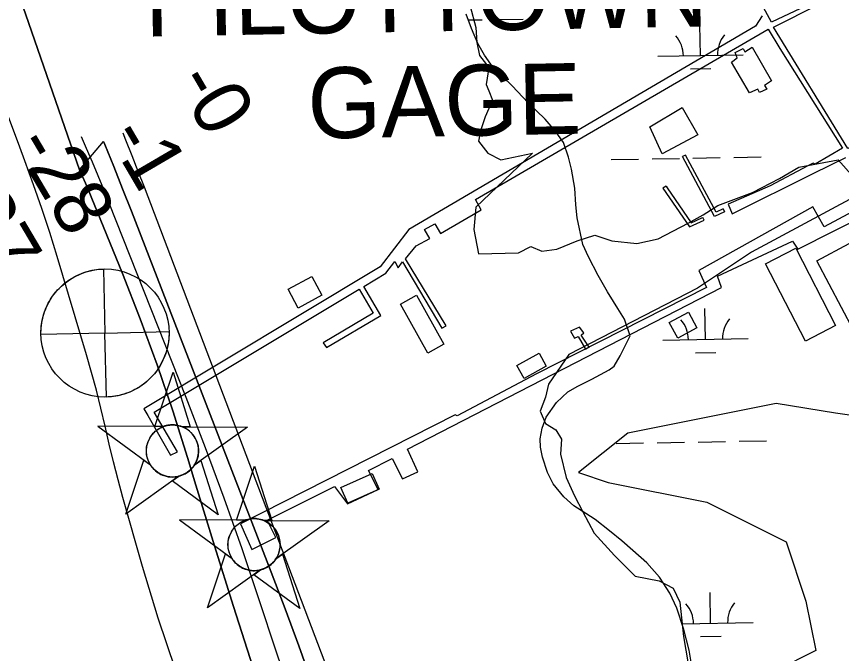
# Model space of a CAD drawing. Extents: x 3914892 to 3953151, y 242587 to 268572.
# Drawn here: x 3942580 to 3943546, y 252639 to 253385 of the extents above; entities that cross this region are included whole.
import ezdxf

# ---------------------------------------------------------------- set-up
doc = ezdxf.new("R2010")
doc.units = 0
for name, color, linetype in [('V-BLDG-OTLN', 7, 'Continuous'), ('V-CHAN-DOCK', 7, 'Continuous'), ('V-CHAN-NAID', 7, 'Continuous'), ('V-RIVR-EDGE', 7, 'Continuous'), ('V-RIVR-GAGE', 7, 'Continuous'), ('V-RIVR-GAGE-IDEN', 7, 'Continuous'), ('V-RIVR-RANG', 7, 'Continuous'), ('V-SITE-VEGE', 7, 'Continuous'), ('V-TOPO-DPTH', 7, 'Continuous'), ('V-TOPO-MINR', 7, 'Continuous'), ('V-WETL-SWMP', 7, 'Continuous')]:
    doc.layers.add(name, color=color, linetype=linetype)

msp = doc.modelspace()

# ---------------------------------------------------------------- linework, layer by layer
at = {"layer": 'V-BLDG-OTLN'}
for points in [[(3943417, 253331.86), (3943423.67, 253336.87), (3943421.34, 253343.11), (3943430.75, 253348.15), (3943432.92, 253344.14), (3943441.29, 253349.45), (3943463.91, 253309.93), (3943455.8, 253304.48), (3943458.62, 253300.32), (3943449.81, 253296.52), (3943447.9, 253300.14), (3943438.29, 253295.95)], [(3943336.08, 253224.42), (3943321.33, 253256.07), (3943359.56, 253278.89), (3943377.83, 253246.94)], [(3943517.03, 253099.31), (3943555.12, 253119.5), (3943566.64, 253097.78), (3943579.97, 253104.84), (3943589.66, 253086.57), (3943583.06, 253083.07), (3943593.52, 253063.35), (3943585.51, 253059.11), (3943597.32, 253036.84), (3943560.5, 253017.32)], [(3943492.55, 253113.96), (3943539.11, 253023.37), (3943503.75, 253005.2), (3943457.19, 253095.79)], [(3942909.55, 253043.89), (3942897.75, 253065.86), (3942925.67, 253080.85), (3942937.47, 253058.88)], [(3943061.36, 252991.07), (3943029.5, 253048.56), (3943048.19, 253058.92), (3943080.04, 253001.42)], [(3943344.27, 253026.99), (3943366.66, 253039.2), (3943376.69, 253020.81), (3943354.31, 253008.6)], [(3943165.83, 252976.54), (3943191.84, 252990.9), (3943200.23, 252975.7), (3943174.22, 252961.33)], [(3942959.64, 252833.66), (3942996.27, 252849.94), (3943004.41, 252831.62), (3942967.78, 252815.34)]]:
    msp.add_lwpolyline(points, close=True, dxfattribs=at)
at = {"layer": 'V-CHAN-DOCK'}
for points in [[(3943517.92, 253404.24), (3943463.83, 253378.69), (3943440.14, 253422.8)], [(3943769.62, 252904.45), (3943816.19, 252933.69), (3943813.48, 252938.9), (3943766.51, 252909.67), (3943720.5, 252982.34), (3943756.42, 253018.48), (3943752.48, 253021.72), (3943717.81, 252989.14), (3943663.2, 253073.87), (3943649.54, 253094.75), (3943601.78, 253155.11), (3943594.76, 253166.35), (3943639.27, 253189.64), (3943635.37, 253196.06), (3943589.27, 253171.99), (3943557.31, 253223.77), (3943607.85, 253252.16), (3943605.92, 253256.57), (3943553.43, 253230.99), (3943466.54, 253373.08), (3943519.85, 253399.84)], [(3943453.19, 253386.4), (3943445.46, 253374.16), (3943039.4, 253135.93), (3943005.77, 253092.19), (3942728.86, 252925.89), (3942733.49, 252918.18), (3942760.13, 252871.42)], [(3942986.34, 253069.25), (3943012.44, 253084.93), (3943022.97, 253098.33), (3943026.86, 253091.11), (3943031.86, 253098.01), (3943077.72, 253020.16), (3943082.89, 253023.24), (3943035.46, 253101.64), (3943047.9, 253116.71), (3943063.94, 253125.25), (3943057.71, 253136.09), (3943069.75, 253142.69), (3943076.36, 253131.06), (3943124.1, 253159.09), (3943117.5, 253171.12), (3943460.14, 253370.78), (3943473.77, 253347.9), (3943547.06, 253231.08), (3943515.36, 253212.39), (3943512.98, 253213.62), (3943506.58, 253210.52), (3943462.47, 253187.22), (3943413.22, 253165.58), (3943417.85, 253154.37), (3943513.63, 253202.06), (3943550.9, 253220.28)], [(3943407.46, 253160.07), (3943399.05, 253156.2), (3943363.32, 253223.17), (3943359.92, 253221.35)], [(3943407.46, 253160.07), (3943409.07, 253156.57), (3943397.36, 253151.19), (3943359.92, 253221.35)], [(3943340.67, 253186.55), (3943336.86, 253184.21), (3943367.8, 253138.89), (3943384.97, 253146.79), (3943383.42, 253149.99)], [(3943340.67, 253186.55), (3943341.72, 253184.77), (3943369.83, 253143.59), (3943382.45, 253149.39), (3943383.42, 253149.99)], [(3943576.04, 253165.8), (3943525.53, 253139), (3943512.3, 253162.27), (3943378.74, 253088.01), (3943388.03, 253067.98), (3943188.82, 252966.74), (3943095.8, 252917.42), (3943093.43, 252918.64), (3942842.12, 252791.02), (3942855.25, 252760.98), (3942883.3, 252774.94), (3942873.23, 252795.38), (3942952.18, 252834.93), (3942967.43, 252814.43), (3943003.49, 252831.46), (3942991.84, 252853.51), (3943019.89, 252867.47), (3943031.92, 252843.82), (3943049.94, 252851.94), (3943037.56, 252878.38), (3943405.55, 253068.15), (3943400.95, 253081.35), (3943488.68, 253122.38), (3943494.92, 253112.74), (3943579.89, 253155.8)], [(3942981.2, 253066.17), (3942997.35, 253038.08), (3942938.96, 253003.23), (3942942.87, 252997.8), (3943006.27, 253035.18), (3942986.34, 253069.25)], [(3942760.13, 252871.42), (3942768.24, 252875.29), (3942740.79, 252921.74), (3942981.2, 253066.17)], [(3943250.31, 252997.99), (3943240.91, 253012.08), (3943244.13, 253014.82), (3943239.04, 253021.66), (3943228.63, 253016.62), (3943233.3, 253008.59), (3943237.7, 253010.53), (3943246.03, 252995.81), (3943250.31, 252997.99)]]:
    msp.add_lwpolyline(points, dxfattribs=at)
at = {"layer": 'V-CHAN-NAID'}
for points in [[(3942751.46, 252905.01), (3942741.87, 252905.08), (3942763, 252968.57), (3942783.22, 252904.79), (3942773.64, 252904.86), (3942772.06, 252905.43), (3942769.96, 252906.05), (3942767.93, 252906.51), (3942765.89, 252906.81), (3942764.72, 252906.93), (3942763.19, 252907.01), (3942761.47, 252907.01), (3942760.1, 252906.94), (3942758.19, 252906.74), (3942756.82, 252906.52), (3942755.04, 252906.13), (3942753.51, 252905.71), (3942752.48, 252905.38)], [(3942751.46, 252905.01), (3942674.97, 252905.56), (3942736.54, 252860.16), (3942735.42, 252862.07), (3942734.61, 252863.69), (3942733.79, 252865.66), (3942733.09, 252867.72), (3942732.73, 252869.04), (3942732.37, 252870.67), (3942732.12, 252872.11), (3942731.93, 252873.71), (3942731.82, 252875.44), (3942731.81, 252877.02), (3942731.92, 252879.1), (3942732.1, 252880.72), (3942732.49, 252882.92), (3942732.98, 252884.84), (3942733.58, 252886.73), (3942734.23, 252888.41), (3942734.96, 252890), (3942735.77, 252891.53), (3942736.83, 252893.27), (3942737.87, 252894.74), (3942738.87, 252896.01), (3942739.87, 252897.15), (3942741.18, 252898.49), (3942742.23, 252899.46), (3942743.95, 252900.85), (3942745.16, 252901.72), (3942746.84, 252902.79), (3942748.58, 252903.74), (3942750.02, 252904.42)], [(3942773.64, 252904.86), (3942850.13, 252904.31), (3942787.93, 252859.79), (3942788.84, 252861.28), (3942789.81, 252863.13), (3942790.53, 252864.71), (3942791.27, 252866.67), (3942791.81, 252868.45), (3942792.21, 252870.09), (3942792.57, 252872.1), (3942792.76, 252873.68), (3942792.88, 252875.88), (3942792.85, 252877.94), (3942792.67, 252880.16), (3942792.4, 252881.92), (3942791.91, 252884.15), (3942791.27, 252886.29), (3942790.52, 252888.27), (3942789.87, 252889.72), (3942788.86, 252891.63), (3942787.8, 252893.36), (3942786.59, 252895.06), (3942785.33, 252896.6), (3942784.05, 252897.96), (3942782.42, 252899.49), (3942780.68, 252900.91), (3942779, 252902.08), (3942777.11, 252903.22), (3942775.64, 252903.98)], [(3942769.9, 252846.89), (3942707.69, 252802.36), (3942728.82, 252865.85), (3942736.54, 252860.16), (3942737.17, 252859.19), (3942738.55, 252857.33), (3942739.77, 252855.92), (3942741.23, 252854.42), (3942742.62, 252853.16), (3942744.08, 252852.01), (3942745.48, 252851.02), (3942747.16, 252849.99), (3942748.87, 252849.07), (3942750.66, 252848.26), (3942752.11, 252847.71), (3942753.73, 252847.18), (3942755.96, 252846.61), (3942757.49, 252846.33), (3942759.52, 252846.07), (3942761.06, 252845.97), (3942762.92, 252845.94), (3942764.6, 252846.02), (3942766.31, 252846.2), (3942768.22, 252846.51)], [(3942787.93, 252859.79), (3942795.72, 252865.37), (3942815.95, 252801.6), (3942762.1, 252841.31), (3942769.9, 252846.89), (3942771.56, 252847.36), (3942773.17, 252847.92), (3942775.33, 252848.84), (3942777.07, 252849.72), (3942778.93, 252850.83), (3942780.67, 252852.05), (3942782.22, 252853.29), (3942783.51, 252854.46), (3942784.89, 252855.88), (3942786.1, 252857.28), (3942787.22, 252858.75)], [(3942847.06, 252795.23), (3942837.47, 252795.3), (3942858.6, 252858.78), (3942878.82, 252795.01), (3942869.23, 252795.08), (3942867.66, 252795.65), (3942865.56, 252796.27), (3942863.52, 252796.72), (3942861.48, 252797.03), (3942860.32, 252797.15), (3942858.78, 252797.23), (3942857.06, 252797.23), (3942855.69, 252797.15), (3942853.79, 252796.95), (3942852.42, 252796.74), (3942850.64, 252796.35), (3942849.11, 252795.93), (3942848.07, 252795.6)], [(3942847.06, 252795.23), (3942770.57, 252795.77), (3942832.13, 252750.38), (3942831.02, 252752.28), (3942830.21, 252753.91), (3942829.38, 252755.88), (3942828.69, 252757.93), (3942828.32, 252759.26), (3942827.96, 252760.88), (3942827.72, 252762.33), (3942827.53, 252763.93), (3942827.42, 252765.66), (3942827.41, 252767.24), (3942827.52, 252769.32), (3942827.7, 252770.93), (3942828.09, 252773.14), (3942828.57, 252775.06), (3942829.17, 252776.95), (3942829.83, 252778.63), (3942830.56, 252780.21), (3942831.37, 252781.75), (3942832.43, 252783.49), (3942833.46, 252784.96), (3942834.46, 252786.23), (3942835.46, 252787.37), (3942836.77, 252788.71), (3942837.82, 252789.67), (3942839.54, 252791.07), (3942840.75, 252791.94), (3942842.44, 252793.01), (3942844.17, 252793.96), (3942845.62, 252794.64)], [(3942869.23, 252795.08), (3942945.73, 252794.53), (3942883.52, 252750.01), (3942884.43, 252751.5), (3942885.41, 252753.35), (3942886.13, 252754.93), (3942886.87, 252756.89), (3942887.41, 252758.67), (3942887.81, 252760.31), (3942888.17, 252762.32), (3942888.35, 252763.89), (3942888.48, 252766.1), (3942888.45, 252768.16), (3942888.26, 252770.38), (3942888, 252772.14), (3942887.5, 252774.37), (3942886.86, 252776.51), (3942886.11, 252778.49), (3942885.47, 252779.94), (3942884.46, 252781.85), (3942883.4, 252783.57), (3942882.18, 252785.28), (3942880.92, 252786.82), (3942879.65, 252788.18), (3942878.02, 252789.71), (3942876.27, 252791.12), (3942874.59, 252792.3), (3942872.71, 252793.43), (3942871.23, 252794.2)], [(3942865.49, 252737.1), (3942803.29, 252692.58), (3942824.41, 252756.07), (3942832.13, 252750.38), (3942832.77, 252749.41), (3942834.15, 252747.55), (3942835.36, 252746.14), (3942836.83, 252744.63), (3942838.22, 252743.38), (3942839.67, 252742.23), (3942841.07, 252741.24), (3942842.75, 252740.2), (3942844.47, 252739.29), (3942846.26, 252738.48), (3942847.7, 252737.93), (3942849.33, 252737.4), (3942851.56, 252736.83), (3942853.09, 252736.55), (3942855.11, 252736.29), (3942856.65, 252736.18), (3942858.51, 252736.16), (3942860.2, 252736.24), (3942861.91, 252736.42), (3942863.81, 252736.73)], [(3942883.52, 252750.01), (3942891.32, 252755.59), (3942911.54, 252691.81), (3942857.69, 252731.52), (3942865.49, 252737.1), (3942867.16, 252737.58), (3942868.77, 252738.14), (3942870.93, 252739.05), (3942872.66, 252739.94), (3942874.53, 252741.05), (3942876.27, 252742.26), (3942877.82, 252743.51), (3942879.11, 252744.68), (3942880.49, 252746.1), (3942881.69, 252747.5), (3942882.81, 252748.97)]]:
    msp.add_lwpolyline(points, close=True, dxfattribs=at)
for centre in [(3942762.35, 252876.48), (3942857.94, 252766.7)]:
    msp.add_circle(centre, 30.54, dxfattribs=at)
at = {"layer": 'V-RIVR-EDGE'}
for points in [[(3943111.08, 253397.55), (3943117.63, 253372.46), (3943118.72, 253355), (3943121.99, 253339.73), (3943132.9, 253325.54), (3943129.63, 253305.91), (3943132.9, 253298.27), (3943137.26, 253287.36), (3943128.54, 253267.72), (3943123.08, 253251.36), (3943120.9, 253239.36), (3943131.81, 253225.18), (3943147.08, 253217.54), (3943184.17, 253225.18), (3943117.63, 253161.9), (3943115.44, 253135.72), (3943120.9, 253107.36), (3943167.81, 253108.45), (3943181.99, 253116.08), (3943195.08, 253110.63), (3943212.54, 253112.81), (3943236.54, 253122.63), (3943257.27, 253129.17), (3943276.9, 253122.63), (3943306.36, 253119.36), (3943331.45, 253124.81), (3943366.36, 253143.36), (3943383.82, 253153.18), (3943401.27, 253164.08), (3943441.64, 253179.36), (3943473.27, 253195.72), (3943496.18, 253208.81), (3943542, 253217.54), (3943560.55, 253196.81)], [(3943560.55, 253173.9), (3943440.55, 253109.54), (3943377.27, 253066.99), (3943226.72, 252989.53), (3943202.72, 252954.62), (3943199.45, 252939.35), (3943192.9, 252922.99), (3943199.45, 252908.8), (3943211.45, 252901.17), (3943217.99, 252890.26), (3943216.9, 252872.8), (3943223.45, 252845.53), (3943233.27, 252823.71), (3943243.08, 252805.16), (3943256.18, 252780.07), (3943280.18, 252753.89), (3943304.18, 252729.89), (3943332.54, 252724.43), (3943348.91, 252715.71), (3943356.54, 252699.34), (3943360.91, 252658.98), (3943369.63, 252608.79)]]:
    msp.add_lwpolyline(points, dxfattribs=at)
at = {"layer": 'V-RIVR-GAGE'}
for points in [[(3942681.64, 253089.61), (3942683.31, 253014.63), (3942608.33, 253012.96), (3942608.31, 253015.06), (3942608.37, 253017.63), (3942608.55, 253020.63), (3942608.85, 253023.6), (3942609.23, 253026.37), (3942609.77, 253029.37), (3942610.34, 253031.96), (3942610.95, 253034.35), (3942611.65, 253036.77), (3942612.56, 253039.53), (3942613.44, 253041.89), (3942614.39, 253044.22), (3942615.53, 253046.75), (3942616.9, 253049.49), (3942618.2, 253051.85), (3942619.54, 253054.11), (3942621.87, 253057.64), (3942623.51, 253059.9), (3942625.67, 253062.62), (3942627.76, 253065.03), (3942629.56, 253066.93), (3942632.27, 253069.58), (3942634.56, 253071.63), (3942636.98, 253073.6), (3942640.04, 253075.89), (3942642.38, 253077.48), (3942644.93, 253079.07), (3942647.87, 253080.73), (3942650.48, 253082.06), (3942653.04, 253083.25), (3942656.64, 253084.73), (3942659.86, 253085.87), (3942663.01, 253086.83), (3942666.25, 253087.66), (3942669.63, 253088.37), (3942673.67, 253089.01), (3942676.66, 253089.33), (3942679.2, 253089.51)], [(3942684.98, 252939.65), (3942683.31, 253014.63), (3942758.29, 253016.3), (3942758.3, 253013.64), (3942758.19, 253010.48), (3942758, 253007.88), (3942757.72, 253005.27), (3942757.26, 253002.13), (3942756.69, 252999.12), (3942755.9, 252995.78), (3942755.31, 252993.62), (3942754.4, 252990.75), (3942753.35, 252987.81), (3942752.31, 252985.24), (3942751.18, 252982.72), (3942749.96, 252980.24), (3942748.67, 252977.85), (3942747.09, 252975.18), (3942745.65, 252972.93), (3942743.6, 252970.01), (3942741.52, 252967.34), (3942738.96, 252964.35), (3942736.72, 252961.98), (3942734.29, 252959.62), (3942732.15, 252957.71), (3942730.54, 252956.37), (3942727.94, 252954.35), (3942726.05, 252953), (3942723.57, 252951.35), (3942720.95, 252949.76), (3942718.27, 252948.27), (3942716.17, 252947.21), (3942713.92, 252946.16), (3942711.33, 252945.06), (3942708.64, 252944.04), (3942705.39, 252942.95), (3942702.25, 252942.06), (3942699.84, 252941.47), (3942697.09, 252940.9), (3942694.72, 252940.5), (3942691.94, 252940.12), (3942689.75, 252939.9), (3942687.18, 252939.73)]]:
    msp.add_lwpolyline(points, close=True, dxfattribs=at)
msp.add_circle((3942683.31, 253014.63), 75, dxfattribs=at)
at = {"layer": 'V-SITE-VEGE'}
msp.add_lwpolyline([(3943620.15, 252908.96), (3943539.05, 252920.54), (3943469.54, 252932.13), (3943295.76, 252897.37), (3943237.84, 252851.03), (3943272.59, 252839.44), (3943388.44, 252816.27), (3943481.13, 252769.93), (3943504.3, 252700.42), (3943515.88, 252642.5), (3943469.54, 252619.33)], dxfattribs=at)
at = {"layer": 'V-TOPO-DPTH'}
for points in [[(3942765.88, 252620.36), (3942745.78, 252680.5), (3942727.27, 252741.21), (3942704.38, 252821.97), (3942698.69, 252842.77), (3942693.25, 252863.62), (3942688.17, 252884.57), (3942683.35, 252905.58), (3942678.48, 252926.58), (3942673.31, 252947.5), (3942667.68, 252968.3), (3942661.74, 252989.02), (3942627.37, 253104.14), (3942618.6, 253132.38), (3942609.44, 253160.49), (3942599.67, 253188.39), (3942589.51, 253216.16), (3942583.4, 253232.3), (3942292.57, 254010.13)], [(3942765.88, 252620.36), (3942745.78, 252680.5), (3942727.27, 252741.21), (3942704.38, 252821.97), (3942698.69, 252842.77), (3942693.25, 252863.62), (3942688.17, 252884.57), (3942683.35, 252905.58), (3942678.48, 252926.58), (3942673.31, 252947.5), (3942667.68, 252968.3), (3942661.74, 252989.02), (3942627.37, 253104.14), (3942618.6, 253132.38), (3942609.44, 253160.49), (3942599.67, 253188.39), (3942589.51, 253216.16), (3942583.4, 253232.3), (3942292.57, 254010.13)], [(3942401.61, 253932.54), (3942653.43, 253205.99), (3942657, 253198.09), (3942660.5, 253190.15), (3942663.89, 253182.16), (3942667.21, 253174.15), (3942703.77, 253084.29), (3942724.57, 253031.06), (3942744.37, 252977.47), (3942762.67, 252923.35), (3942779.97, 252868.88), (3942789.86, 252836.2), (3942811.61, 252765.2), (3942833.72, 252694.32), (3942856.35, 252623.6)], [(3942653.43, 253205.99), (3942681.52, 253239.15), (3942683.01, 253235.6), (3942693.63, 253209.67), (3942704.02, 253183.65), (3942714.25, 253157.56), (3942877.99, 252734.29), (3942894.28, 252691.37), (3942910.21, 252648.32), (3942925.59, 252605.07), (3942940.61, 252561.69), (3942955.68, 252518.33), (3942971.2, 252475.14), (3942987.37, 252432.18), (3943003.98, 252389.39), (3943048.18, 252278.06), (3943056.89, 252256.46), (3943065.75, 252234.92), (3943074.84, 252213.48), (3943084.09, 252192.11), (3943134.63, 252076.98), (3943325.96, 251461.72)], [(3942856.35, 252623.6), (3942833.72, 252694.32), (3942811.61, 252765.2), (3942789.86, 252836.2), (3942779.97, 252868.88), (3942762.67, 252923.35), (3942744.37, 252977.47), (3942724.57, 253031.06), (3942703.77, 253084.29), (3942667.21, 253174.15), (3942663.89, 253182.16), (3942660.5, 253190.15), (3942657, 253198.09), (3942653.43, 253205.99)]]:
    msp.add_lwpolyline(points, dxfattribs=at)
at = {"layer": 'V-TOPO-MINR'}
for points in [[(3942765.88, 252620.36), (3942745.78, 252680.5), (3942727.27, 252741.21), (3942704.38, 252821.97), (3942698.69, 252842.77), (3942693.25, 252863.62), (3942688.17, 252884.57), (3942683.35, 252905.58), (3942678.48, 252926.58), (3942673.31, 252947.5), (3942667.68, 252968.3), (3942661.74, 252989.02), (3942627.37, 253104.14), (3942618.6, 253132.38), (3942609.44, 253160.49), (3942599.67, 253188.39), (3942589.51, 253216.16), (3942583.4, 253232.3), (3942292.57, 254010.13)], [(3942856.35, 252623.6), (3942833.72, 252694.32), (3942811.61, 252765.2), (3942789.86, 252836.2), (3942779.97, 252868.88), (3942762.67, 252923.35), (3942744.37, 252977.47), (3942724.57, 253031.06), (3942703.77, 253084.29), (3942667.21, 253174.15), (3942663.89, 253182.16), (3942660.5, 253190.15), (3942657, 253198.09), (3942653.43, 253205.99), (3942401.61, 253932.54)], [(3942904.14, 252582.34), (3942883.8, 252642.04), (3942863.92, 252701.9), (3942843.83, 252761.68), (3942823, 252821.19), (3942801.08, 252880.31), (3942778.43, 252939.17), (3942688.4, 253166.74), (3942681.93, 253182.84), (3942675.34, 253198.89), (3942668.56, 253214.87), (3942661.66, 253230.8), (3942655.71, 253244.35)], [(3943528.63, 251037.74), (3943087.65, 252247.67), (3943083.46, 252257.31), (3943079.33, 252266.99), (3943056.43, 252321.65), (3943047.03, 252344.66), (3943037.91, 252367.78), (3943029.22, 252391.06), (3943020.81, 252414.45), (3943012.51, 252437.88), (3943004.09, 252461.27), (3942995.48, 252484.59), (3942986.75, 252507.87), (3942729.41, 253185.34), (3942722.31, 253203.82), (3942715.13, 253222.27), (3942707.81, 253240.67), (3942704.55, 253248.76)], [(3943325.96, 251461.72), (3943134.63, 252076.98), (3943084.09, 252192.11), (3943074.84, 252213.48), (3943065.75, 252234.92), (3943056.89, 252256.46), (3943048.18, 252278.06), (3943003.98, 252389.39), (3942987.37, 252432.18), (3942971.2, 252475.14), (3942955.68, 252518.33), (3942940.61, 252561.69), (3942925.59, 252605.07), (3942910.21, 252648.32), (3942894.28, 252691.37), (3942877.99, 252734.29), (3942714.25, 253157.56), (3942704.02, 253183.65), (3942693.63, 253209.67), (3942683.01, 253235.6), (3942681.52, 253239.15)]]:
    msp.add_lwpolyline(points, dxfattribs=at)
at = {"layer": 'V-WETL-SWMP'}
for p, q in [((3943112.62, 253371.27), (3943106.26, 253387.99)), ((3943108.78, 253381.36), (3943125.13, 253381.65)), ((3943141.13, 253381.94), (3943173.12, 253382.51)), ((3943119.93, 253353.96), (3943112.62, 253371.27)), ((3943380.76, 253339.79), (3943380.12, 253375.78)), ((3943127.68, 253340.31), (3943119.93, 253353.96)), ((3943138.12, 253325.67), (3943127.68, 253340.31)), ((3943330.77, 253338.9), (3943430.75, 253340.68)), ((3943160.27, 253304.09), (3943138.12, 253325.67)), ((3943369.04, 253324.15), (3943393.04, 253324.58)), ((3943179.16, 253284.3), (3943160.27, 253304.09)), ((3943199.02, 253265.08), (3943179.16, 253284.3)), ((3943210.64, 253251.39), (3943199.02, 253265.08)), ((3943220.32, 253237.72), (3943210.64, 253251.39)), ((3943226.28, 253220.62), (3943220.32, 253237.72)), ((3943229.77, 253206.64), (3943226.28, 253220.62)), ((3943276.08, 253217.83), (3943308.08, 253218.4)), ((3943324.08, 253218.69), (3943356.07, 253219.26)), ((3943372.07, 253219.54), (3943404.06, 253220.12)), ((3943420.06, 253220.4), (3943452.06, 253220.98)), ((3943233.73, 253184.35), (3943229.77, 253206.64)), ((3943234.82, 253164.99), (3943233.73, 253184.35)), ((3943236.36, 253149.69), (3943234.82, 253164.99)), ((3943242.91, 253118.46), (3943236.36, 253149.69)), ((3943249.48, 253103.86), (3943242.91, 253118.46)), ((3943260.99, 253082.04), (3943249.48, 253103.86)), ((3943271.96, 253062.94), (3943260.99, 253082.04)), ((3943278.96, 253051.43), (3943271.96, 253062.94)), ((3943284.08, 253043.43), (3943278.96, 253051.43)), ((3943291.65, 253030.76), (3943284.08, 253043.43)), ((3943386.71, 253007.17), (3943386.07, 253043.16)), ((3943298.35, 253011.52), (3943291.65, 253030.76)), ((3943286.82, 252987.88), (3943298.35, 253011.52)), ((3943336.72, 253006.27), (3943436.71, 253008.06)), ((3943374.99, 252991.52), (3943398.99, 252991.95)), ((3943279.69, 252975.79), (3943286.82, 252987.88)), ((3943274.03, 252971.61), (3943279.69, 252975.79)), ((3943253.57, 252960.67), (3943274.03, 252971.61)), ((3943237.21, 252952.37), (3943253.57, 252960.67)), ((3943212, 252933.17), (3943225.52, 252945.76)), ((3943225.52, 252945.76), (3943237.21, 252952.37)), ((3943200.17, 252916.11), (3943212, 252933.17)), ((3943195.35, 252903.02), (3943200.17, 252916.11)), ((3943193.06, 252890.68), (3943195.35, 252903.02)), ((3943193.32, 252881), (3943193.06, 252890.68)), ((3943282.03, 252885.21), (3943314.03, 252885.78)), ((3943330.03, 252886.06), (3943362.02, 252886.64)), ((3943378.02, 252886.92), (3943410.01, 252887.49)), ((3943426.01, 252887.78), (3943458.01, 252888.35)), ((3943195.67, 252869.17), (3943193.32, 252881)), ((3943201.63, 252851.29), (3943195.67, 252869.17)), ((3943208.22, 252838.05), (3943201.63, 252851.29)), ((3943220.59, 252822.8), (3943208.22, 252838.05)), ((3943232.44, 252812.2), (3943220.59, 252822.8)), ((3943246.63, 252803.11), (3943232.44, 252812.2)), ((3943257.37, 252796), (3943246.63, 252803.11)), ((3943274.41, 252783.01), (3943257.37, 252796)), ((3943288.76, 252771.21), (3943274.41, 252783.01)), ((3943301.77, 252759.82), (3943288.76, 252771.21)), ((3943317.82, 252745.48), (3943301.77, 252759.82)), ((3943332.69, 252728.65), (3943317.82, 252745.48)), ((3943344.82, 252709.92), (3943332.69, 252728.65)), ((3943353.28, 252692.2), (3943344.82, 252709.92)), ((3943392.66, 252674.55), (3943392.02, 252710.54)), ((3943361.46, 252667.14), (3943353.28, 252692.2)), ((3943359.24, 252673.95), (3943442.66, 252675.44)), ((3943367.52, 252643.08), (3943361.46, 252667.14)), ((3943380.94, 252658.9), (3943404.94, 252659.33)), ((3943370.75, 252624.27), (3943367.52, 252643.08))]:
    msp.add_line(p, q, dxfattribs=at)
for centre, start, end in [((3943325.52, 253339.28), 0.25318, 41.79684), ((3943435.99, 253341.25), 140.25318, 181.79684), ((3943331.47, 253006.65), 0.25318, 41.79684), ((3943441.94, 253008.63), 140.25318, 181.79684), ((3943337.42, 252674.03), 0.25318, 41.79684), ((3943447.89, 252676.01), 140.25318, 181.79684)]:
    msp.add_arc(centre, 35.25, start, end, dxfattribs=at)

# ---------------------------------------------------------------- texts
at = {"layer": 'V-RIVR-GAGE-IDEN'}
for s, p in [('PILOTTOWN', (3942730.47, 253361.83)), ('GAGE', (3942921.23, 253242.29))]:
    msp.add_text(s, height=83, rotation=1.04604, dxfattribs=at).set_placement(p)
at = {"layer": 'V-RIVR-RANG'}
for s, rotation, p in [('-0', 300.30833, (3942763.92, 253309.13)), ('-1', 300.30833, (3942685.16, 253245.71)), ('-28', 300.58694, (3942575.12, 253235)), ('-37', 300.58694, (3942488.77, 253184.57))]:
    msp.add_text(s, height=67, rotation=rotation, dxfattribs=at).set_placement(p)

doc.saveas('drawing.dxf')
